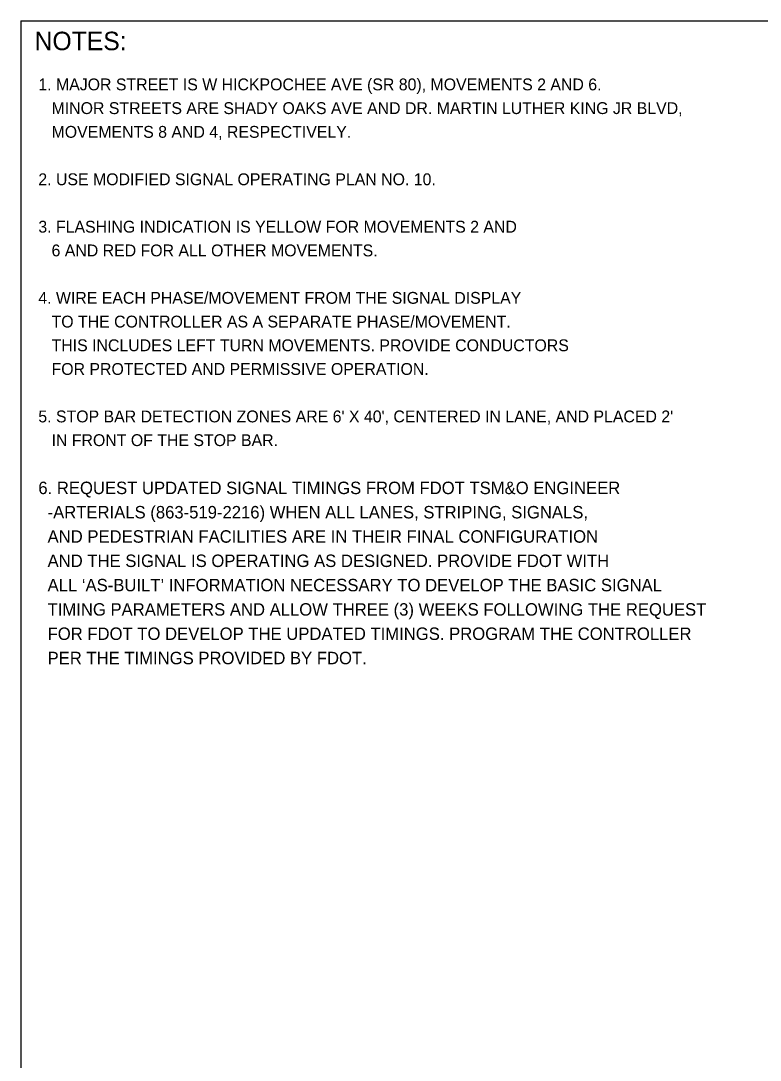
# Model space of a CAD drawing. Extents: x 0 to 1428, y -128 to 567.
# Drawn here: x 0.0458 to 0.3791, y 0.4022 to 0.8708 of the extents above; entities that cross this region are included whole.
import ezdxf

# ---------------------------------------------------------------- set-up
doc = ezdxf.new("R2010")
doc.units = 0
doc.layers.add('SheetBorder_dp', color=7, linetype='Continuous')
doc.layers.add('TextLabel', color=7, linetype='Continuous')

msp = doc.modelspace()

# ---------------------------------------------------------------- linework, layer by layer
at = {"layer": 'SheetBorder_dp'}
for q in [(0.04583, 0.00417), (1.32916, 0.87083)]:
    msp.add_line((0.04583, 0.87083), q, dxfattribs=at)

# ---------------------------------------------------------------- texts
at = {"layer": 'TextLabel'}
for s, height, p in [('NOTES:', 0.008333, (0.05205, 0.85757)), ('1. MAJOR STREET IS W HICKPOCHEE AVE (SR 80), MOVEMENTS 2 AND 6. ', 0.0053458, (0.05374, 0.83947)), ('   MINOR STREETS ARE SHADY OAKS AVE AND DR. MARTIN LUTHER KING JR BLVD, ', 0.0053458, (0.05374, 0.82878)), ('   MOVEMENTS 8 AND 4, RESPECTIVELY.', 0.0053458, (0.05374, 0.81808)), ('2. USE MODIFIED SIGNAL OPERATING PLAN NO. 10.', 0.0053458, (0.05374, 0.7967)), ('3. FLASHING INDICATION IS YELLOW FOR MOVEMENTS 2 AND ', 0.0053458, (0.05374, 0.77532)), ('   6 AND RED FOR ALL OTHER MOVEMENTS.', 0.0053458, (0.05374, 0.76463)), ('4. WIRE EACH PHASE/MOVEMENT FROM THE SIGNAL DISPLAY ', 0.0053458, (0.05374, 0.74324)), ('   TO THE CONTROLLER AS A SEPARATE PHASE/MOVEMENT. ', 0.0053458, (0.05374, 0.73255)), ('   THIS INCLUDES LEFT TURN MOVEMENTS. PROVIDE CONDUCTORS ', 0.0053458, (0.05374, 0.72186)), ('   FOR PROTECTED AND PERMISSIVE OPERATION.', 0.0053458, (0.05374, 0.71117)), ("5. STOP BAR DETECTION ZONES ARE 6' X 40', CENTERED IN LANE, AND PLACED 2'", 0.0053458, (0.05374, 0.68978)), ('   IN FRONT OF THE STOP BAR.', 0.0053458, (0.05374, 0.67909)), ('6. REQUEST UPDATED SIGNAL TIMINGS FROM FDOT TSM&O ENGINEER ', 0.0056123, (0.05374, 0.65744)), ('  -ARTERIALS (863-519-2216) WHEN ALL LANES, STRIPING, SIGNALS, ', 0.0056123, (0.05374, 0.64648)), ('  AND PEDESTRIAN FACILITIES ARE IN THEIR FINAL CONFIGURATION ', 0.0056123, (0.05374, 0.63553)), ('  AND THE SIGNAL IS OPERATING AS DESIGNED. PROVIDE FDOT WITH ', 0.0056123, (0.05374, 0.62457)), ('  ALL ‘AS-BUILT’ INFORMATION NECESSARY TO DEVELOP THE BASIC SIGNAL ', 0.0056123, (0.05374, 0.61361)), ('  TIMING PARAMETERS AND ALLOW THREE (3) WEEKS FOLLOWING THE REQUEST', 0.0056123, (0.05374, 0.60265)), ('  FOR FDOT TO DEVELOP THE UPDATED TIMINGS. PROGRAM THE CONTROLLER ', 0.0056123, (0.05374, 0.59169)), ('  PER THE TIMINGS PROVIDED BY FDOT.', 0.0056123, (0.05374, 0.58074))]:
    msp.add_text(s, height=height, dxfattribs=at).set_placement(p)

doc.saveas('drawing.dxf')
